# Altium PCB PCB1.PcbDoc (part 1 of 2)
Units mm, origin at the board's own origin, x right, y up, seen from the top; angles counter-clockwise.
Board outline 200 x 200.6 mm, 2 copper layers (Top Layer, Bottom Layer); 119 components, 156 nets, 629 pads, 125 vias.
Unrouted connection lines stored in the file: 2.
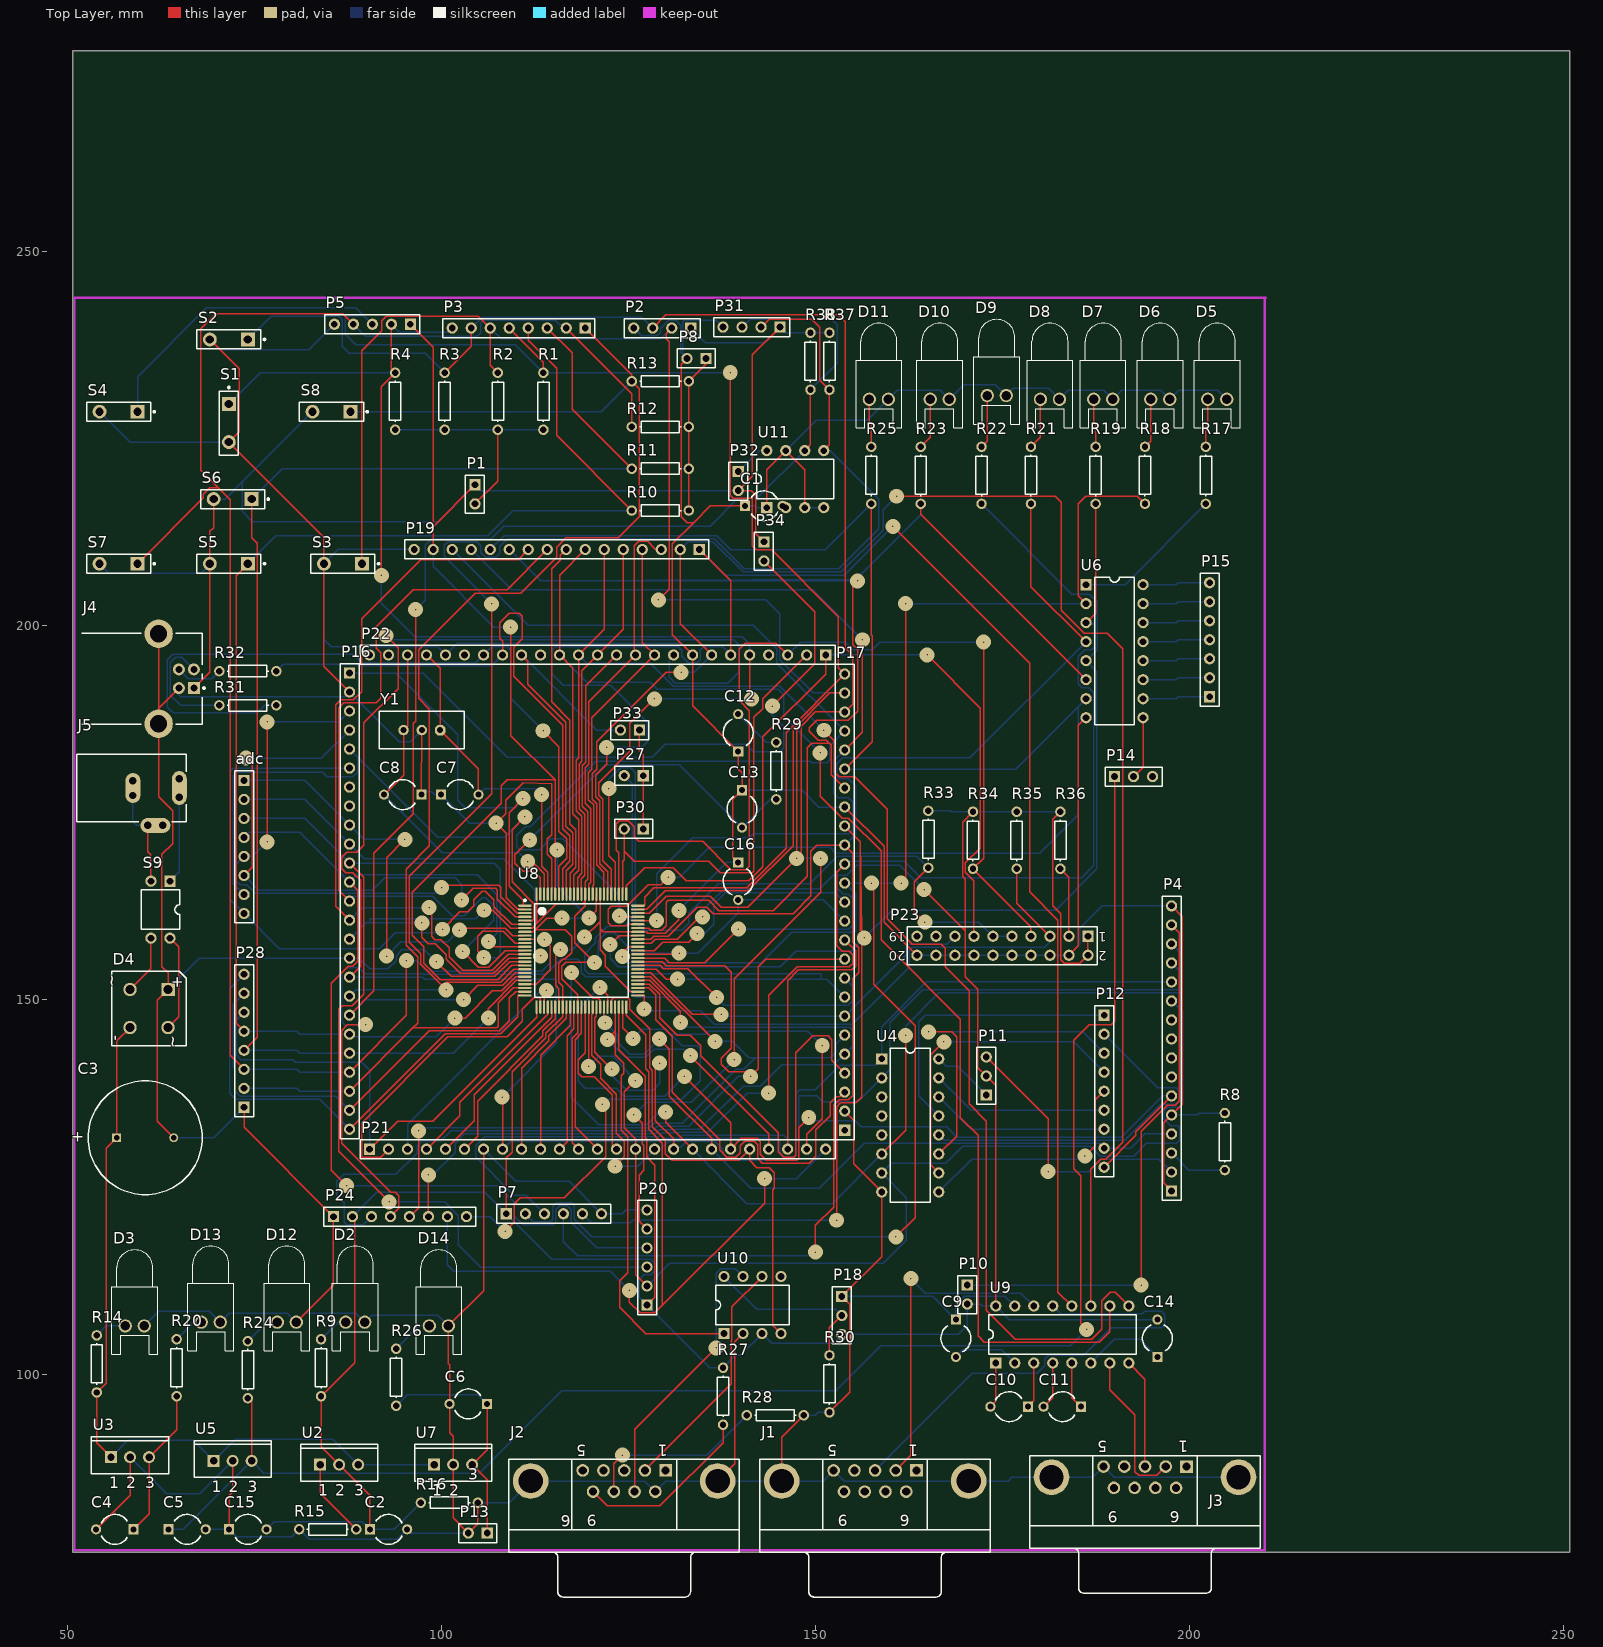
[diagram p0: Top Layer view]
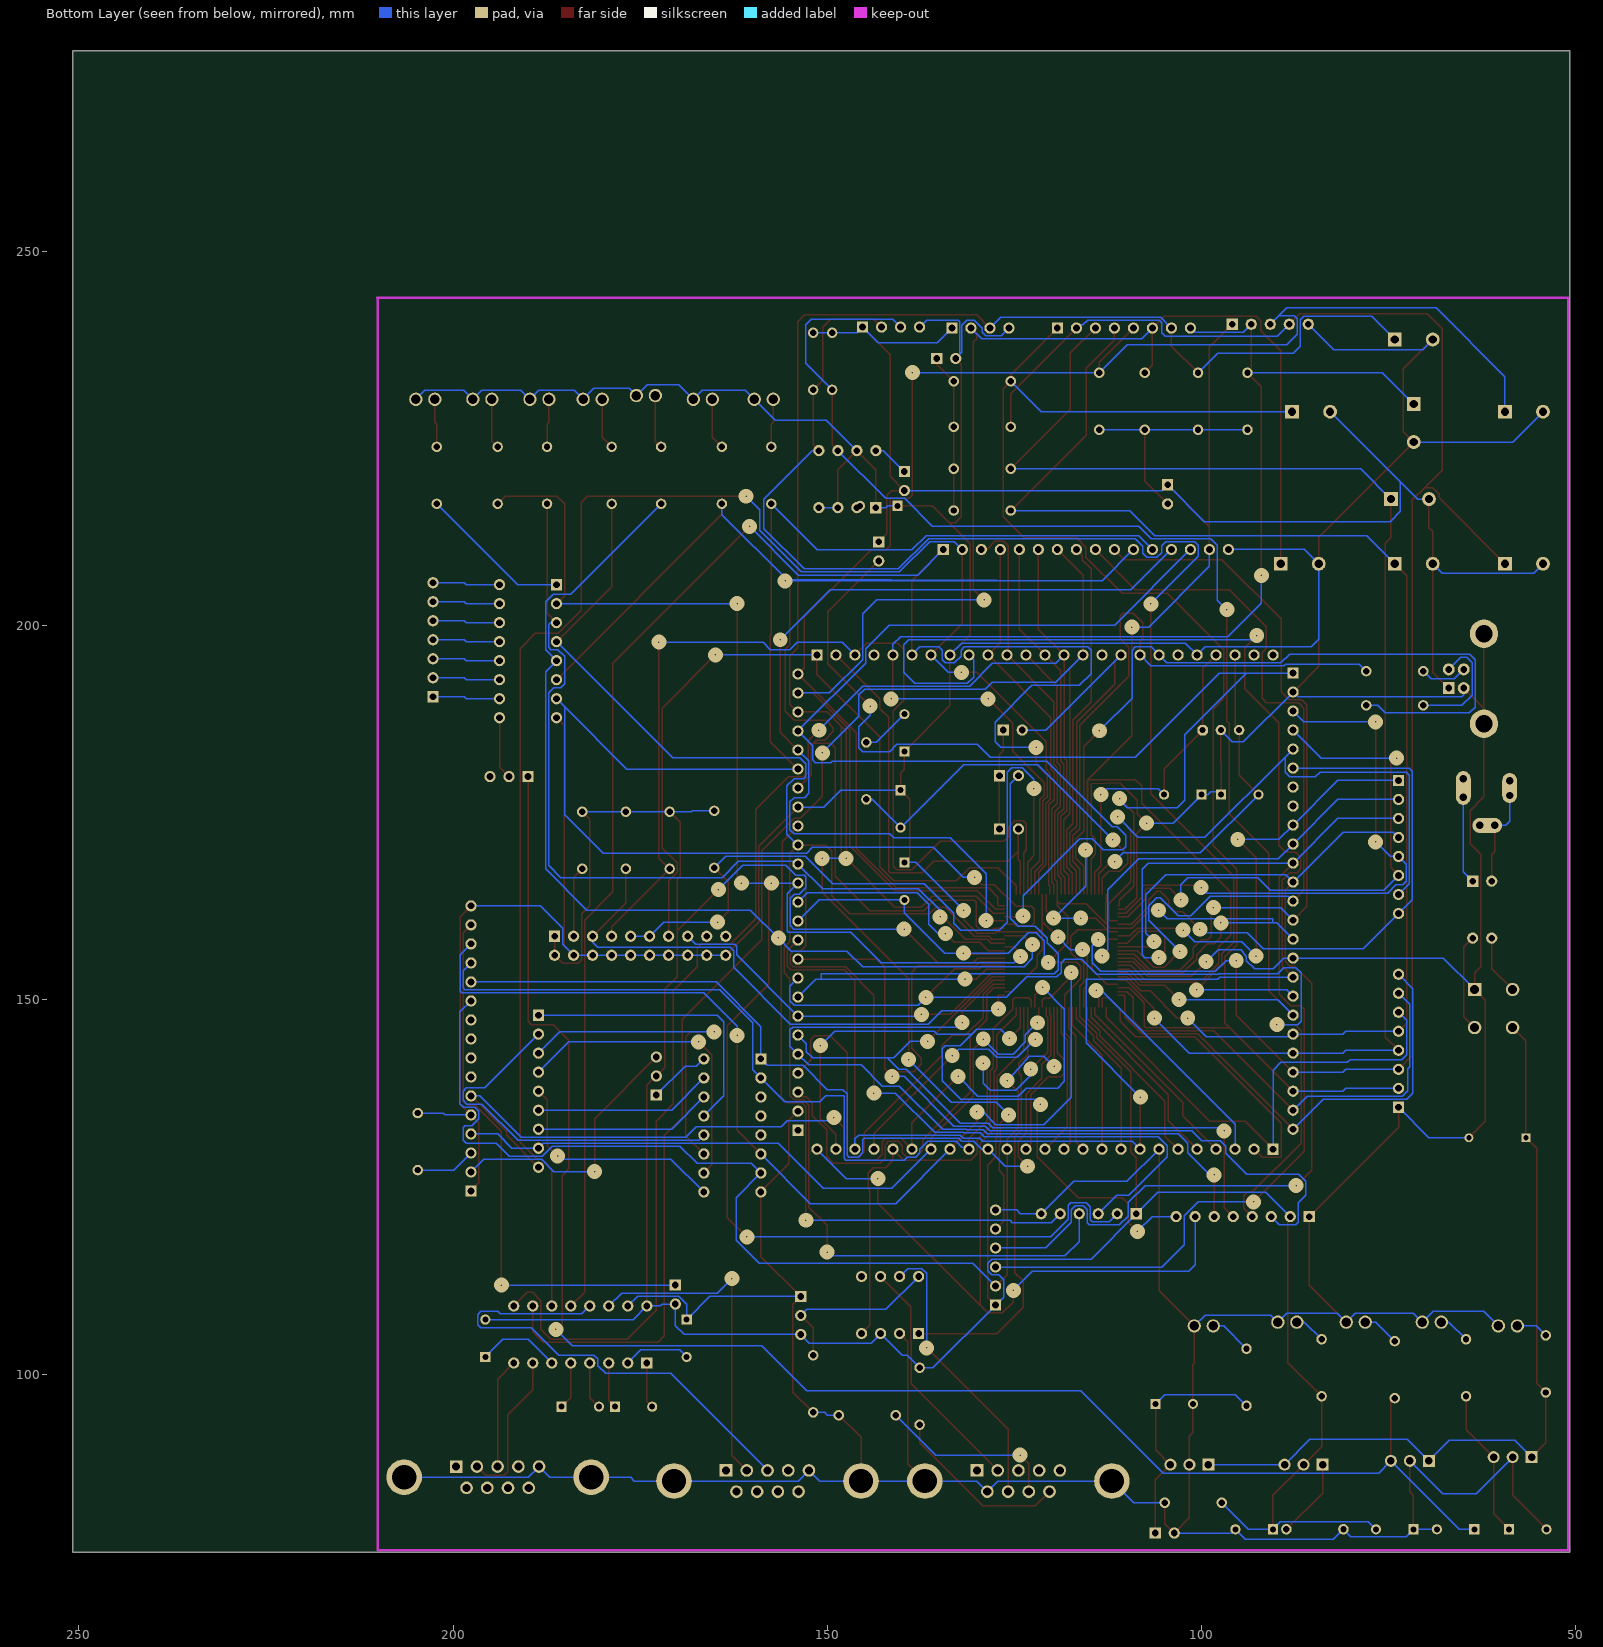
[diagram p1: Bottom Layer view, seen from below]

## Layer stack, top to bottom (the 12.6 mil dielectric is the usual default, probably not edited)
Top Layer: signal copper 0.0356
Dielectric: dielectric 0.32, FR-4, Dk 4.8
Bottom Layer: signal copper 0.0356

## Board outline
50.8,76.2 250.8,76.2 250.8,276.8 50.8,276.8

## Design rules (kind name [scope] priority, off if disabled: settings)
Clearance [All] p1: gap=0.2
ComponentClearance [All] p1: gap=0.254 collisioncheckmode=3 verticalgap=0.254
PolygonConnect [All] p1: connectstyle=Relief reliefconductorwidth=0.254 reliefentries=4 polygonreliefangle="90 Angle"
RoomDefinition relevance [InComponentClass('relevance')] p1: confinementstyle=ConfineIn formatcopy=TRUE lockcomponents=FALSE outline 0,0 50.8,0 50.8,25.4 0,25.4
RoutingVias [All] p1: holewidth=0.2 width=2 viastyle="Through Hole" minholewidth=0.711 minwidth=1.27 maxholewidth=0.711 maxwidth=1.27
SolderMaskExpansion [All] p1: expansion=0.102
TestPointUsage [All] p1: valid=0 allowmultiple=FALSE
Testpoint [All] p1: side=15 testpointundercomponent=TRUE minsize=1.016 maxsize=2.54 preferedsize=1.524 minholesize=0 maxholesize=1.016 preferedholesize=0.813 testpointgrid=0.025 style=1023 order=0123456789
Width [All] p1: maxlimit=0.2 minlimit=0.2 preferedwidth=0.2
18 further rules are at their usual default settings.

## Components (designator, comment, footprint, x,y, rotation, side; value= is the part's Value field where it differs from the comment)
adc "Header 8" HDR1X8 73.66,179.324 r270 top
C1 "Cap2" CAPR5-4X5 143.129,216.027 r0 top
C2 "Cap2" CAPR5-4X5 92.964,79.248 r0 top
C3 "Cap Pol1" RB7.6-15 60.452,131.572 r180 top
C4 "Cap2" CAPR5-4X5 56.388,79.248 r180 top
C5 "Cap2" CAPR5-4X5 66.04,79.248 r0 top
C6 "Cap2" CAPR5-4X5 103.632,96.012 r180 top
C7 "Cap2" CAPR5-4X5 102.489,177.419 r0 top
C8 "Cap2" CAPR5-4X5 94.869,177.419 r180 top
C9 "Cap2" CAPR5-4X5 168.783,104.775 r270 top
C10 "Cap2" CAPR5-4X5 175.895,95.631 r180 top
C11 "Cap2" CAPR5-4X5 183.007,95.631 r180 top
C12 "Cap2" CAPR5-4X5 139.7,185.674 r90 top
C13 "Cap2" CAPR5-4X5 140.208,175.514 r270 top
C14 "Cap2" CAPR5-4X5 195.707,104.775 r90 top
C15 "Cap2" CAPR5-4X5 74.168,79.248 r0 top
C16 "Cap2" CAPR5-4X5 139.7,165.862 r270 top
D2 "LED0" LED-0 88.519,106.934 r180 top
D3 "LED0" LED-0 59.055,106.426 r180 top
D4 "Bridge1" D-38 60.96,148.844 r270 top
D5 "LED0" LED-0 203.708,230.251 r180 top
D6 "LED0" LED-0 196.088,230.251 r180 top
D7 "LED0" LED-0 188.468,230.251 r180 top
D8 "LED0" LED-0 181.356,230.251 r180 top
D9 "LED0" LED-0 174.244,230.759 r180 top
D10 "LED0" LED-0 166.624,230.251 r180 top
D11 "LED0" LED-0 158.496,230.251 r180 top
D12 "LED0" LED-0 79.375,106.934 r180 top
D13 "LED0" LED-0 69.215,106.934 r180 top
D14 "LED0" LED-0 99.695,106.426 r180 top
J1 "D Connector 9" DSUB1.385-2H9 157.988,76.2 r180 top
J2 "D Connector 9" DSUB1.385-2H9 124.46,76.2 r180 top
J3 "D Connector 9" DSUB1.385-2H9 194.056,76.708 r180 top
J4 "1-1470156-1" 1-1470156 51.943,192.913 r180 top
J5 "PWR2.5" KLD-0202 51.308,178.308 r0 top
P1 "pad/sw" HDR1X2 104.521,218.821 r270 top
P2 "Debug Unit" HDR1X4 133.35,239.776 r180 top
P3 "keypad4*4" HDR1X8 119.253,239.776 r180 top
P4 "LCD2*16" HDR1X16 197.612,124.46 r90 top
P5 "Interrupt" HDR1X5 95.885,240.284 r180 top
P7 "pwm" HDR1X6 108.712,121.412 r0 top
P8 "pad/sw" HDR1X2 135.382,235.712 r180 top
P10 "LIGHT on/off" HDR1X2 170.307,111.887 r270 top
P11 "lcd/7seg" HDR1X3 172.847,137.287 r90 top
P12 "7SEGMENT*2" HDR1X9 188.595,147.955 r270 top
P13 "Header 2" HDR1X2 106.172,78.74 r180 top
P14 "5v/12v" HDR1X3 189.992,179.832 r0 top
P15 "12/5 v . 500ma out" HDR1X7 202.692,190.5 r90 top
P16 "1-25" HDR1X25 87.757,193.675 r270 top
P17 "51-75" HDR1X25 153.924,132.588 r90 top
P18 "Header 3" HDR1X3 153.543,110.363 r270 top
P19 "USART" HDR1X16 134.493,210.185 r180 top
P20 "Programmable Clock Output" HDR1X6 127.508,109.22 r90 top
P21 "26-50" HDR1X25 90.424,130.048 r0 top
P22 "76-100" HDR1X25 151.384,196.088 r180 top
P23 "Header 10X2" HDR2X10 186.436,158.496 r180 top
P24 "Synchronous Serial Controller" HDR1X8 85.598,121.031 r0 top
P27 "TST" HDR1X2 127,179.959 r180 top
P28 "Serial Peripheral Interface (SPI)" HDR1X8 73.66,135.636 r90 top
P30 "ERASE" HDR1X2 127,172.847 r180 top
P31 "2-wire" HDR1X4 145.288,239.903 r180 top
P32 "Header 2" HDR1X2 139.7,220.599 r270 top
P33 "JTAGSEL" HDR1X2 126.492,186.055 r180 top
P34 "Header 2" HDR1X2 143.129,211.201 r270 top
R1 "Res1" AXIAL-0.3 113.665,229.997 r270 top
R2 "Res1" AXIAL-0.3 107.569,229.997 r270 top
R3 "Res1" AXIAL-0.3 100.457,229.997 r270 top
R4 "Res1" AXIAL-0.3 93.853,229.997 r270 top
R8 "Res1" AXIAL-0.3 204.724,131.064 r90 top
R9 "Res1" AXIAL-0.3 83.947,100.838 r90 top
R10 "Res1" AXIAL-0.3 129.286,215.392 r180 top
R11 "Res1" AXIAL-0.3 129.286,220.98 r180 top
R12 "Res1" AXIAL-0.3 129.286,226.568 r180 top
R13 "Res1" AXIAL-0.3 129.286,232.664 r180 top
R14 "Res1" AXIAL-0.3 53.975,101.346 r90 top
R15 "Res1" AXIAL-0.3 84.836,79.248 r0 top
R16 "Res1" AXIAL-0.3 101.092,82.804 r180 top
R17 "Res1" AXIAL-0.3 202.184,220.091 r90 top
R18 "Res1" AXIAL-0.3 194.056,220.091 r90 top
R19 "Res1" AXIAL-0.3 187.452,220.091 r90 top
R20 "Res1" AXIAL-0.3 64.643,100.838 r90 top
R21 "Res1" AXIAL-0.3 178.816,220.091 r90 top
R22 "Res1" AXIAL-0.3 172.212,220.091 r90 top
R23 "Res1" AXIAL-0.3 164.084,220.091 r90 top
R24 "Res1" AXIAL-0.3 74.168,100.584 r90 top
R25 "Res1" AXIAL-0.3 157.48,220.091 r90 top
R26 "Res1" AXIAL-0.3 93.98,99.568 r90 top
R27 "Res1" AXIAL-0.3 137.668,97.028 r90 top
R28 "Res1" AXIAL-0.3 144.653,94.488 r0 top
R29 "Res1" AXIAL-0.3 144.78,180.594 r270 top
R30 "Res1" AXIAL-0.3 151.892,98.679 r90 top
R31 "Res1" AXIAL-0.3 74.168,189.357 r0 top
R32 "Res1" AXIAL-0.3 74.168,193.929 r0 top
R33 "Res1" AXIAL-0.3 165.1,171.45 r90 top
R34 "Res1" AXIAL-0.3 171.069,171.323 r90 top
R35 "Res1" AXIAL-0.3 176.911,171.323 r90 top
R36 "Res1" AXIAL-0.3 182.753,171.323 r90 top
R37 "Res1" AXIAL-0.3 151.892,235.331 r90 top
R38 "Res1" AXIAL-0.3 149.352,235.331 r90 top
S1 "SW-PB" SPST-2 71.628,227.076 r270 top
S2 "SW-PB" SPST-2 71.628,238.252 r180 top
S3 "SW-PB" SPST-2 86.868,208.28 r180 top
S4 "SW-PB" SPST-2 56.896,228.6 r180 top
S5 "SW-PB" SPST-2 71.628,208.28 r180 top
S6 "SW-PB" SPST-2 72.136,216.916 r180 top
S7 "SW-PB" SPST-2 56.896,208.28 r180 top
S8 "SW-PB" SPST-2 85.344,228.6 r180 top
S9 "SW DIP-2" DIP-4 62.484,162.052 r180 top
U2 "LM317T" 221A-04 86.36,87.884 r0 top
U3 "MC78M12BT" 221A-04 58.42,88.9 r0 top
U4 "DM7447AN" N16E 162.687,133.223 r270 top
U5 "MC78M05CT" 221A-04 72.136,88.392 r0 top
U6 "ULN2003A" A16 189.992,196.596 r270 top
U7 "MC78M05CT" 221A-04 101.6,87.884 r0 top
U8 "AT91SAM7X256-AU" LQFP100_N 118.745,156.591 r0 top
U9 "MAX232ACPE" PE16A 183.007,105.283 r0 top
U10 "MCP2551-E/P" PDIP300-8 141.605,109.22 r0 top
U11 "ST24E256B6" PSDIP8A 147.32,219.583 r0 top
Y1 "ECS-49-20-4-3IL" HC-49US 97.409,186.055 r180 top

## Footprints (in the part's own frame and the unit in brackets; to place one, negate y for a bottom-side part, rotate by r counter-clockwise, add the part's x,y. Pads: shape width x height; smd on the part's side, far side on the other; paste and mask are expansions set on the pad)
1-1470156 [mm] "Connector; USB1.1, Type B, Thru-Hole; 4 Position; Right Angle"
  rect 1.6x1.6 hole 0.92: 1(-15.01,1.25)
  round 1.6 hole 0.92: 2(-15.01,-1.25) 3(-13.01,-1.25) 4(-13.01,1.25)
  round 3.8 hole 2.3: 5(-10.3,6.02) 6(-10.3,-6.02)
  silkscreen extent -16.49,-6.05 -0.02,6.05
221A-04 [mm] "TO, Thru-Hole, Vertical, Heatsink Mounted; 3 In-Line Leads; Pitch 2.54 mm"
  rect 1.6x1.6 hole 1: 1(-2.54,0)
  round 1.6 hole 1: 2(0,0) 3(2.54,0)
  silkscreen extent -5.15,-2.2 5.15,2.7
A16 [mm] "DIP; 16 Leads; Row Spacing 7.62 mm; Pitch 2.54 mm"
  rect 1.5x1.5 hole 0.9: 1(-8.89,-3.81)
  round 1.5 hole 0.9: 2(-6.35,-3.81) 3(-3.81,-3.81) 4(-1.27,-3.81) 5(1.27,-3.81) 6(3.81,-3.81) 7(6.35,-3.81) 8(8.89,-3.81) 9(8.89,3.81) 10(6.35,3.81) 11(3.81,3.81) 12(1.27,3.81) 13(-1.27,3.81) 14(-3.81,3.81) 15(-6.35,3.81) 16(-8.89,3.81)
  silkscreen extent -9.85,-2.65 9.85,2.65
AXIAL-0.3 [mm] "Resistor; 2 Leads"
  round 1.4 hole 0.85: 1(-3.81,0) 2(3.81,0)
  silkscreen extent -2.77,-0.76 2.77,0.76
CAPR5-4X5 [mm] "Capacitor; 2 Leads"
  rect 1.35x1.35 hole 0.8: 1(-2.5,0)
  round 1.35 hole 0.8: 2(2.5,0)
  silkscreen extent -1.69,-2 1.82,2
D-38 [mm] "Bridge Rectifier; 4 Terminals; Body 9.4 x 9.4 mm (typ); Pitch 5.08 mm"
  rect 1.8x1.8 hole 1.2: 1(-2.54,2.54)
  round 1.8 hole 1.2: 2(-2.54,-2.54) 3(2.54,-2.54) 4(2.54,2.54)
  silkscreen extent -5,-5 5,5
DIP-4 [mm] "DIP; 4 Leads; Row Spacing 7.62 mm; Pitch 2.54 mm"
  rect 1.5x1.5 hole 0.9: 1(-1.27,-3.81)
  round 1.5 hole 0.9: 2(1.27,-3.81) 3(1.27,3.81) 4(-1.27,3.81)
  silkscreen extent -2.55,-2.65 2.55,2.65
DSUB1.385-2H9 [mm] "Connector; D Subminiature; 9 Position; Right Angle; Pitch 1.385 mm"
  rect 1.69x1.69 hole 1.09: 1(-5.54,-10.92)
  round 1.69 hole 1.09: 2(-2.77,-10.92) 3(0,-10.92) 4(2.77,-10.92) 5(5.54,-10.92) 6(-4.155,-8.08) 7(-1.385,-8.08) 8(1.385,-8.08) 9(4.155,-8.08)
  round 4.76 hole 3.26: 10(-12.495,-9.5) 11(12.495,-9.5)
  silkscreen extent -15.4,-12.4 15.4,6
HC-49US [mm] "Quartz Crystal, Thru-Hole; 3 Leads; Body 11.35 x 5 x 3.5 mm (LxWxH max)"
  oct 1.4x1.4 hole 0.8: 1(-2.44,0)
  round 1.4 hole 0.8: 2(0,0) 3(2.44,0)
  silkscreen extent -5.7,-2.5 5.7,2.5
HDR1X2 [mm] "Connector; Header; 2 Position"
  rect 1.5x1.5 hole 0.9: 1(0,0)
  round 1.5 hole 0.9: 2(2.54,0)
  silkscreen extent -1.27,-1.27 3.81,1.27
HDR1X3 [mm] "Connector; Header; 3 Position"
  rect 1.5x1.5 hole 0.9: 1(0,0)
  round 1.5 hole 0.9: 2(2.54,0) 3(5.08,0)
  silkscreen extent -1.27,-1.27 6.35,1.27
HDR1X4 [mm] "Connector; Header; 4 Position"
  rect 1.5x1.5 hole 0.9: 1(0,0)
  round 1.5 hole 0.9: 2(2.54,0) 3(5.08,0) 4(7.62,0)
  silkscreen extent -1.27,-1.27 8.89,1.27
HDR1X5 [mm] "Connector; Header; 5 Position"
  rect 1.5x1.5 hole 0.9: 1(0,0)
  round 1.5 hole 0.9: 2(2.54,0) 3(5.08,0) 4(7.62,0) 5(10.16,0)
  silkscreen extent -1.27,-1.27 11.43,1.27
HDR1X6 [mm] "Connector; Header; 6 Position"
  rect 1.5x1.5 hole 0.9: 1(0,0)
  round 1.5 hole 0.9: 2(2.54,0) 3(5.08,0) 4(7.62,0) 5(10.16,0) 6(12.7,0)
  silkscreen extent -1.27,-1.27 13.97,1.27
HDR1X7 [mm] "Connector; Header; 7 Position"
  rect 1.5x1.5 hole 0.9: 1(0,0)
  round 1.5 hole 0.9: 2(2.54,0) 3(5.08,0) 4(7.62,0) 5(10.16,0) 6(12.7,0) 7(15.24,0)
  silkscreen extent -1.27,-1.27 16.51,1.27
HDR1X8 [mm] "Connector; Header; 8 Position"
  rect 1.5x1.5 hole 0.9: 1(0,0)
  round 1.5 hole 0.9: 2(2.54,0) 3(5.08,0) 4(7.62,0) 5(10.16,0) 6(12.7,0) 7(15.24,0) 8(17.78,0)
  silkscreen extent -1.27,-1.27 19.05,1.27
HDR1X9 [mm] "Connector; Header; 9 Position"
  rect 1.5x1.5 hole 0.9: 1(0,0)
  round 1.5 hole 0.9: 2(2.54,0) 3(5.08,0) 4(7.62,0) 5(10.16,0) 6(12.7,0) 7(15.24,0) 8(17.78,0) 9(20.32,0)
  silkscreen extent -1.27,-1.27 21.59,1.27
HDR1X16 [mm] "Connector; Header; 16 Position"
  rect 1.5x1.5 hole 0.9: 1(0,0)
  round 1.5 hole 0.9: 2(2.54,0) 3(5.08,0) 4(7.62,0) 5(10.16,0) 6(12.7,0) 7(15.24,0) 8(17.78,0) 9(20.32,0) 10(22.86,0) 11(25.4,0) 12(27.94,0) 13(30.48,0) 14(33.02,0) 15(35.56,0) 16(38.1,0)
  silkscreen extent -1.27,-1.27 39.37,1.27
HDR1X25 [mm] "Connector; Header; 25 Position"
  rect 1.5x1.5 hole 0.9: 1(0,0)
  round 1.5 hole 0.9: 2(2.54,0) 3(5.08,0) 4(7.62,0) 5(10.16,0) 6(12.7,0) 7(15.24,0) 8(17.78,0) 9(20.32,0) 10(22.86,0) 11(25.4,0) 12(27.94,0) 13(30.48,0) 14(33.02,0) 15(35.56,0) 16(38.1,0) 17(40.64,0) 18(43.18,0) 19(45.72,0) 20(48.26,0) 21(50.8,0) 22(53.34,0) 23(55.88,0) 24(58.42,0) 25(60.96,0)
  silkscreen extent -1.27,-1.27 62.23,1.27
HDR2X10 [mm] "Connector; Header; 10x2 Position"
  rect 1.5x1.5 hole 0.9: 1(0,0)
  round 1.5 hole 0.9: 2(0,2.54) 3(2.54,0) 4(2.54,2.54) 5(5.08,0) 6(5.08,2.54) 7(7.62,0) 8(7.62,2.54) 9(10.16,0) 10(10.16,2.54) 11(12.7,0) 12(12.7,2.54) 13(15.24,0) 14(15.24,2.54) 15(17.78,0) 16(17.78,2.54) 17(20.32,0) 18(20.32,2.54) 19(22.86,0) 20(22.86,2.54)
  silkscreen extent -1.27,-1.27 24.13,3.81
KLD-0202 [mm] "DC Power Jack, 2.5mm, KLD Series, PCB Mount"
  oval 2x4.5 all layers, no hole: 1(13.7,0)
  round 1.5 hole 1: 1A(13.7,-1.25) 1B(13.7,1.25) 2A(7.5,-1) 2B(7.5,1) 3A(9.5,-5) 3B(11.5,-5)
  oval 2x4 all layers, no hole: 2(7.5,0)
  oval 4x2 all layers, no hole: 3(10.5,-5)
  silkscreen extent 0,-4.5 14.6,4.5
LED-0 [mil] "Typical INFRARED GaAs LED; 2 Leads"
  round 70 hole 50: 1(50,0) 2(-50,0)
  silkscreen extent -120,-400 120,150
LQFP100_N [mm] "Thin QFP, 100-Leads, Body 14x14mm, Pitch 0.5mm, IPC Medium Density"
  oval 1.8x0.3 smd: 1(-7.55,6) 2(-7.55,5.5) 3(-7.55,5) 4(-7.55,4.5) 5(-7.55,4) 6(-7.55,3.5) 7(-7.55,3) 8(-7.55,2.5) 9(-7.55,2) 10(-7.55,1.5) 11(-7.55,1) 12(-7.55,0.5) 13(-7.55,0) 14(-7.55,-0.5) 15(-7.55,-1) 16(-7.55,-1.5) 17(-7.55,-2) 18(-7.55,-2.5) 19(-7.55,-3) 20(-7.55,-3.5) 21(-7.55,-4) 22(-7.55,-4.5) 23(-7.55,-5) 24(-7.55,-5.5) 25(-7.55,-6) 51(7.55,-6) 52(7.55,-5.5) 53(7.55,-5) 54(7.55,-4.5) 55(7.55,-4) 56(7.55,-3.5) 57(7.55,-3) 58(7.55,-2.5) 59(7.55,-2) 60(7.55,-1.5) 61(7.55,-1) 62(7.55,-0.5) 63(7.55,0) 64(7.55,0.5) 65(7.55,1) 66(7.55,1.5) 67(7.55,2) 68(7.55,2.5) 69(7.55,3) 70(7.55,3.5) 71(7.55,4) 72(7.55,4.5) 73(7.55,5) 74(7.55,5.5) 75(7.55,6)
  oval 0.3x1.8 smd: 26(-6,-7.55) 27(-5.5,-7.55) 28(-5,-7.55) 29(-4.5,-7.55) 30(-4,-7.55) 31(-3.5,-7.55) 32(-3,-7.55) 33(-2.5,-7.55) 34(-2,-7.55) 35(-1.5,-7.55) 36(-1,-7.55) 37(-0.5,-7.55) 38(0,-7.55) 39(0.5,-7.55) 40(1,-7.55) 41(1.5,-7.55) 42(2,-7.55) 43(2.5,-7.55) 44(3,-7.55) 45(3.5,-7.55) 46(4,-7.55) 47(4.5,-7.55) 48(5,-7.55) 49(5.5,-7.55) 50(6,-7.55) 76(6,7.55) 77(5.5,7.55) 78(5,7.55) 79(4.5,7.55) 80(4,7.55) 81(3.5,7.55) 82(3,7.55) 83(2.5,7.55) 84(2,7.55) 85(1.5,7.55) 86(1,7.55) 87(0.5,7.55) 88(0,7.55) 89(-0.5,7.55) 90(-1,7.55) 91(-1.5,7.55) 92(-2,7.55) 93(-2.5,7.55) 94(-3,7.55) 95(-3.5,7.55) 96(-4,7.55) 97(-4.5,7.55) 98(-5,7.55) 99(-5.5,7.55) 100(-6,7.55)
  silkscreen extent -7.67,-6.25 6.25,6.82, body extent -7,-7 7,7, height 1.6
N16E [mm] "DIP; 16 Leads; Row Spacing 7.62 mm; Pitch 2.54 mm"
  rect 1.5x1.5 hole 0.9: 1(-8.89,-3.81)
  round 1.5 hole 0.9: 2(-6.35,-3.81) 3(-3.81,-3.81) 4(-1.27,-3.81) 5(1.27,-3.81) 6(3.81,-3.81) 7(6.35,-3.81) 8(8.89,-3.81) 9(8.89,3.81) 10(6.35,3.81) 11(3.81,3.81) 12(1.27,3.81) 13(-1.27,3.81) 14(-3.81,3.81) 15(-6.35,3.81) 16(-8.89,3.81)
  silkscreen extent -10.3,-2.65 10.3,2.65
PDIP300-8 [mm] "DIP, Plastic; 8 Leads; Row Spacing 7.62 mm; Pitch 2.54 mm"
  rect 1.5x1.5 hole 0.9: 1(-3.81,-3.81)
  round 1.5 hole 0.9: 2(-1.27,-3.81) 3(1.27,-3.81) 4(3.81,-3.81) 5(3.81,3.81) 6(1.27,3.81) 7(-1.27,3.81) 8(-3.81,3.81)
  silkscreen extent -4.9,-2.65 4.9,2.65
PE16A [mm] "DIP; 16 Leads; Row Spacing 7.62 mm; Pitch 2.54 mm"
  rect 1.5x1.5 hole 0.9: 1(-8.89,-3.81)
  round 1.5 hole 0.9: 2(-6.35,-3.81) 3(-3.81,-3.81) 4(-1.27,-3.81) 5(1.27,-3.81) 6(3.81,-3.81) 7(6.35,-3.81) 8(8.89,-3.81) 9(8.89,3.81) 10(6.35,3.81) 11(3.81,3.81) 12(1.27,3.81) 13(-1.27,3.81) 14(-3.81,3.81) 15(-6.35,3.81) 16(-8.89,3.81)
  silkscreen extent -9.85,-2.65 9.85,2.65
PSDIP8A [mm] "DIP; 8 Leads; Row Spacing 7.62 mm; Pitch 2.54 mm"
  rect 1.5x1.5 hole 0.9: 1(-3.81,-3.81)
  round 1.5 hole 0.9: 2(-1.27,-3.81) 3(1.27,-3.81) 4(3.81,-3.81) 5(3.81,3.81) 6(1.27,3.81) 7(-1.27,3.81) 8(-3.81,3.81)
  silkscreen extent -5.15,-2.65 5.15,2.65
RB7.6-15 [mm] "Polarized Capacitor (Radial); 2 Leads"
  rect 1.2x1.2 hole 0.7: 1(3.81,0)
  round 1.2 hole 0.7: 2(-3.81,0)
  silkscreen extent -7.62,-7.62 7.62,7.62
SPST-2 [mm] "Circuit Breaker; 2 Leads"
  rect 1.85x1.85 hole 1.1: 1(-2.54,0)
  round 1.85 hole 1.1: 2(2.54,0)
  silkscreen extent -4.89,-1.27 4.28,1.27

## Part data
adc: "Header, 8-Pin"
C1 C2 C4 C5 C6 C7 C8 C9 C10 C11 C12 C13 C14 C15 C16: "Capacitor"
C3: "Polarized Capacitor (Radial)"
D2 D3 D5 D6 D7 D8 D9 D10 D11 D12 D13 D14: "Typical INFRARED GaAs LED"
D4: "Full Wave Diode Bridge"
J1 J2 J3: "Receptacle Assembly, 9 Position, Right Angle"
J4: "USB 1.1, Right Angle, Thru-Hole, B Type, Receptacle, 4 Position, White"
J5: "Low Voltage Power Supply Connector"
P1 P8 P10 P27 P30 P33: library part "Header 2", "Header, 2-Pin"
P2 P31: library part "Header 4", "Header, 4-Pin"
P3 P24 P28: library part "Header 8", "Header, 8-Pin"
P4 P19: library part "Header 16", "Header, 16-Pin"
P5: library part "Header 5", "Header, 5-Pin"
P7 P20: library part "Header 6", "Header, 6-Pin"
P11 P14: library part "Header 3", "Header, 3-Pin"
P12: library part "Header 9", "Header, 9-Pin"
P13 P32 P34: "Header, 2-Pin"
P15: library part "Header 7", "Header, 7-Pin"
P16 P17 P21 P22: library part "Header 25", "Header, 25-Pin"
P18: "Header, 3-Pin"
P23: "Header, 10-Pin, Dual row"
R1 R2 R3 R4 R8 R9 R10 R11 R12 R13 R14 R15 R16 R17 R18 R19 R20 R21 R22 R23 R24 R25 R26 R27 R28 R29 R30 R31 R32 R33 R34 R35 R36 R37 R38: "Resistor"
S1 S2 S3 S4 S5 S6 S7 S8: "Switch"
S9: "DIP Switch, 2 Position, SPST"
U2: "3-Terminal Adjustable Positive Voltage Regulator"
U3 U5 U7: "3-Terminal Medium-Current Positive Fixed Voltage Regulator"
U4: "BCD to 7-Segment Decoder/Driver"
U6: "High-Voltage, High-Current Darlington Array"
U8: "Smart ARM Microcontroller, ARM7TDMI 32-Bit RISC CPU, 256KB Flash and 64KB SRAM, 100-Pin LQFP, Industrial, Pb-Free"
U9: "+5V Powered, Multi-Channel RS-232 Driver/Receiver"
U10: "High Speed CAN Transceiver, 8-Pin Plastic DIP, Extended Grade"
U11: "Serial Access Extended Addressing Compatible with I²C Bus 256K (32K x 8) EEPROM"
Y1: "Crystal Oscillator, 3rd In-Line Lead Version"

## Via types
v1: diameter 2, hole 0.2, Top Layer to Bottom Layer, 125 vias

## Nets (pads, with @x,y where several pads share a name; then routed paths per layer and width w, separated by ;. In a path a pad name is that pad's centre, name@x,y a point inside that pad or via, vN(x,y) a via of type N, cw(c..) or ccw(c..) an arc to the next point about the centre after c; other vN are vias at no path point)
5V: C5.1 P14.1 R24.1 U5.3 | length 222.3
  Top Layer w0.2: R24.1@74.168,96.774 74.676,96.266 U5.3@74.676,88.392 ; v1(186.258,105.969) 185.445,106.782 185.445,126.525 184.552,127.419 184.552,144.598 186.639,146.685 189.56,146.685 189.992,147.117 P14.1@189.992,179.832
  Bottom Layer w0.2: C5.1@63.54,79.248 65.532,79.248 U5.3@74.676,88.392 76.302,86.766 105.105,86.766 116.103,97.765 152.73,97.765 158.775,103.81 184.099,103.81 v1(186.258,105.969)
12V: C4.1 R20.1 U3.3 | length 20.2
  Top Layer w0.2: C4.1@58.888,79.248 60.96,81.32 U3.3@60.96,88.9 64.643,92.583 R20.1@64.643,97.028
+12: P14.3
AD4: adc.5 P16.3 U8.3 | length 77.2
  Top Layer w0.2: v1(76.733,171.12) v1(76.733,187.147) ; v1(100.051,164.998) 100.347,165.295 107.696,165.295 107.938,165.053 107.938,163.791 110.138,161.591 U8.3@111.195,161.591
  Bottom Layer w0.2: v1(76.733,171.12) 74.778,169.164 adc.5@73.66,169.164 72.61,168.114 72.61,165.871 73.127,165.354 74.016,165.354 75.125,164.245 99.297,164.245 v1(100.051,164.998) ; v1(76.733,187.147) 86.309,187.147 P16.3@87.757,188.595
AD5: adc.6 P16.4 U8.4 | length 76.2
  Top Layer w0.2: adc.6@73.66,166.624 74.727,167.691 74.727,181.483 v1(73.914,182.296) ; v1(102.743,163.373) 104.265,164.895 107.29,164.895 107.528,164.657 107.528,163.441 109.877,161.091 U8.4@111.195,161.091
  Bottom Layer w0.2: adc.6@73.66,166.624 75.639,164.645 90.807,164.645 92.461,166.298 101.849,166.298 102.743,165.405 v1(102.743,163.373) ; v1(73.914,182.296) 83.998,182.296 P16.4@87.757,186.055
AD6: adc.7 P16.5 U8.5 | length 82.1
  Top Layer w0.2: U8.5@111.195,160.591 112.166,160.591 112.395,160.82 112.395,162.839 109.467,165.768 109.467,172.713 v1(111.201,174.447)
  Bottom Layer w0.2: adc.7@73.66,164.084 72.21,165.534 72.21,179.991 72.61,180.391 84.15,180.391 84.76,179.781 88.189,179.781 88.824,180.416 88.824,182.448 ; P16.5@87.757,183.515 88.824,182.448 ; v1(111.201,174.447) 108.483,171.729 99.543,171.729 88.824,182.448
AD7: adc.8 P16.6 U8.6 | length 81.4
  Top Layer w0.2: v1(100.203,159.436) 102.514,161.747 103.556,161.747 104.369,162.56 104.369,163.373 105.491,164.495 105.913,164.495 107.036,163.373 107.036,162.463 109.408,160.091 U8.6@111.195,160.091
  Bottom Layer w0.2: P16.6@87.757,180.975 72.21,180.975 71.81,180.575 71.81,163.394 adc.8@73.66,161.544 78.359,156.845 91.731,156.845 93.869,158.983 99.75,158.983 v1(100.203,159.436)
ADVREF: C1.2 P16.1 P34.2 U8.1 | length 141
  Top Layer w0.2: v1(110.922,176.886) 109.067,175.031 109.067,165.213 110.973,163.308 110.973,162.591 U8.1@111.195,162.591 ; P34.2@143.129,208.661 149.911,201.879 149.911,194.894 v1(144.272,189.255)
  Bottom Layer w0.2: P16.1@87.757,193.675 94.005,193.675 ; v1(110.922,176.886) 110.922,176.7 109.889,175.666 103.226,175.666 102.235,176.657 102.235,185.445 94.005,193.675 ; v1(144.272,189.255) 144.272,188.036 145.796,186.512 145.796,183.693 145.263,183.159 141.681,183.159 140.691,184.15 129.946,184.15 128.219,182.423 108.864,182.423 97.612,193.675 94.005,193.675
CTS0: P19.5 P22.13 U8.88 | length 49
  Top Layer w0.2: U8.88@118.745,164.141 118.745,166.17 119.195,166.62 119.195,174.776 118.428,175.542 118.428,181.513 118.777,181.861 118.777,193.961 P22.13@120.904,196.088 124.333,199.517 P19.5@124.333,210.185
CTS1: P16.14 P19.10 U8.14 | length 100.8
  Top Layer w0.2: P16.14@87.757,160.655 85.907,162.505 85.907,189.429 86.563,190.085 88.282,190.085 89.357,191.16 89.357,200.92 97.276,208.839 110.287,208.839 P19.10@111.633,210.185 ; v1(98.4,162.331) 98.709,162.022 98.709,158.49 99.162,158.037 99.974,158.037 101.065,156.947 101.065,155.775 102.889,153.951 106.809,153.951 108.949,156.091 U8.14@111.195,156.091
  Bottom Layer w0.2: P16.14@87.757,160.655 89.433,162.331 v1(98.4,162.331)
DB4: P4.11 P20.2 P21.15 U4.7 U8.40 | length 158.4
  Top Layer w0.2: v1(119.693,141.105) 119.693,145.915 119.728,148.382 U8.40@119.745,149.041 ; v1(125.959,139.217) 124.455,137.714 124.455,132.914 125.984,131.385 P21.15@125.984,130.048 125.984,113.284 P20.2@127.508,111.76
  Bottom Layer w0.2: v1(119.693,141.105) 121.051,142.463 123.034,142.463 125.552,139.624 v1(125.959,139.217) ; P20.2@127.508,111.76 130.531,114.783 159.106,114.783 162.179,117.856 162.179,123.571 U4.7@158.877,126.873 160.147,128.143 167.411,128.143 169.702,130.434 186.736,130.434 188.062,129.108 192.532,129.108 194.234,130.81 198.222,130.81 198.679,131.267 198.679,132.893 198.425,133.147 197.51,133.147 196.562,134.095 196.562,135.128 197.104,135.67 198.611,135.67 199.085,136.144 199.085,148.387 P4.11@197.612,149.86
DB5: P4.12 P21.16 U4.1 U8.41 | length 118.6
  Top Layer w0.2: U8.41@120.245,149.041 120.245,148.123 120.128,148.006 120.128,142.61 121.31,141.427 121.31,139.522 123.419,137.414 123.419,132.19 124.494,131.115 124.494,129.015 v1(123.241,127.762)
  Bottom Layer w0.2: v1(123.241,127.762) 126.238,127.762 P21.16@128.524,130.048 129.362,130.048 130.412,131.098 132.01,131.098 132.41,131.498 145.049,131.498 145.254,131.293 145.254,129.613 145.869,128.998 147.117,128.998 147.354,129.235 147.354,137.421 147.93,137.996 149.975,137.996 153.245,141.266 158.03,141.266 U4.1@158.877,142.113 158.877,146.423 164.854,152.4 P4.12@197.612,152.4
DB6: P4.13 P21.17 U4.2 U8.42 | length 125.2
  Top Layer w0.2: U8.42@120.745,149.041 120.745,147.783 120.545,147.583 120.545,143.02 v1(122.809,140.756) ; v1(129.184,141.554) 128.632,141.001 128.632,133.838 131.064,131.406 P21.17@131.064,130.048
  Bottom Layer w0.2: v1(122.809,140.756) 122.809,139.903 124.799,137.914 128.243,137.914 129.184,138.856 v1(129.184,141.554) ; P21.17@131.064,130.048 131.064,130.315 132.017,130.315 132.8,131.098 136.584,131.098 137.634,130.048 137.634,129.54 138.176,128.998 139.334,128.998 139.734,128.598 147.523,128.598 147.754,128.829 147.754,137.163 147.781,137.19 150.19,137.19 150.982,136.398 155.702,136.398 U4.2@158.877,139.573 159.944,140.64 159.944,146.914 164.38,151.35 198.425,151.35 198.662,151.587 198.662,153.89 P4.13@197.612,154.94
DB7: P4.14 P21.18 U4.6 U8.43 | length 139.9
  Top Layer w0.2: v1(117.399,153.67) 117.399,153.137 120.294,150.241 120.966,150.241 121.245,149.962 U8.43@121.245,149.041 ; v1(129.997,135.019) 129.997,133.655 P21.18@133.604,130.048 ; U4.6@158.877,129.413 162.052,132.588 v1(162.052,145.263)
  Bottom Layer w0.2: v1(117.399,153.67) 117.399,136.986 121.065,133.32 127.462,133.32 129.16,135.019 v1(129.997,135.019) ; P21.18@133.604,130.048 140.868,122.784 152.248,122.784 U4.6@158.877,129.413 ; v1(162.052,145.263) 162.052,146.482 166.52,150.95 198.831,150.95 199.062,151.181 199.062,156.03 P4.14@197.612,157.48
DCD1: P17.19 P19.11 R23.1 U6.6 U8.69 | length 221.9
  Top Layer w0.2: U8.69@126.295,159.591 127.716,159.591 128.016,159.291 129.471,159.291 130.099,159.918 130.099,163.043 130.353,163.297 135.738,163.297 137.109,161.925 144.348,161.925 148.92,166.497 148.92,183.693 149.551,184.323 151.871,184.323 ; P17.19@153.924,178.308 152.121,180.111 152.121,184.074 151.871,184.323 ; v1(155.651,205.994) 154.986,205.329 154.986,197.485 155.651,196.82 155.651,188.57 154.432,187.35 150.165,187.35 149.2,186.385 149.2,185.877 150.368,184.709 151.486,184.709 151.871,184.323 ; R23.1@164.084,216.281 164.084,214.884 U6.6@186.182,192.786
  Bottom Layer w0.2: P19.11@109.093,210.185 113.284,205.994 ; v1(155.651,205.994) 113.284,205.994 ; R23.1@164.084,216.281 164.084,214.854 155.438,206.207 113.284,205.994
DDM: P22.18 R32.2 U8.93 | length 80.6
  Top Layer w0.2: P22.18@108.204,196.088 108.204,197.908 107.818,198.293 107.818,200.376 109.093,201.651 110.439,201.651 110.846,201.244 110.846,198.281 109.694,197.129 109.694,193.277 116.245,186.726 116.245,172.85 117.195,171.9 117.195,168.5 116.245,167.55 U8.93@116.245,164.141
  Bottom Layer w0.2: R32.2@77.978,193.929 78.918,194.869 88.743,194.869 88.974,194.638 106.754,194.638 P22.18@108.204,196.088
DDP: P22.19 R31.2 U8.94 | length 105.5
  Top Layer w0.2: v1(113.64,185.959) 115.745,183.854 115.745,172.55 116.795,171.5 116.795,168.9 115.745,167.85 U8.94@115.745,164.141
  Bottom Layer w0.2: R31.2@77.978,189.357 76.429,189.357 75.413,188.341 64.186,188.341 63.424,189.103 63.424,195.478 64.135,196.19 88.231,196.19 89.383,195.038 104.614,195.038 P22.19@105.664,196.088 106.731,197.155 108.814,197.155 109.271,196.698 109.271,190.328 v1(113.64,185.959)
DSR1: P17.20 P19.12 R25.1 U6.7 U8.70 | length 217.3
  Top Layer w0.2: U8.70@126.295,160.091 124.993,160.091 124.787,159.885 122.733,159.885 122.326,160.291 122.326,162.082 122.733,162.488 124.769,162.488 127.691,165.41 129.368,165.41 v1(130.327,166.37) ; P17.20@153.924,180.848 157.591,184.515 157.591,198.653 157.48,198.764 R25.1@157.48,216.281
  Bottom Layer w0.2: P19.12@106.553,210.185 108.403,212.035 136.809,212.035 138.709,210.134 151.333,210.134 R25.1@157.48,216.281 ; v1(130.327,166.37) 131.851,166.37 135.844,170.362 151.998,170.362 152.763,169.598 179.961,169.598 185.115,174.752 185.115,189.179 ; P17.20@153.924,180.848 176.784,180.848 185.115,189.179 ; U6.7@186.182,190.246 185.115,189.179
DTR1: P17.21 P19.13 U8.71 | length 123.5
  Top Layer w0.2: U8.71@126.295,160.591 v1(128.778,160.591) ; P17.21@153.924,183.388 156.286,185.75 v1(156.286,198.12)
  Bottom Layer w0.2: P19.13@104.013,210.185 109.423,204.775 149.631,204.775 v1(156.286,198.12) ; v1(128.778,160.591) 128.778,166.83 133.602,171.653 141.148,171.653 141.673,172.178 154.449,172.178 154.991,172.72 154.991,176.479 154.432,177.038 153.033,177.038 152.474,177.597 152.474,181.938 P17.21@153.924,183.388
E: P4.6 P12.9 P21.20 U8.45 | length 128.3
  Top Layer w0.2: v1(121.213,151.659) 122.245,150.627 U8.45@122.245,149.041 ; v1(132.512,139.776) 138.684,133.604 P21.20@138.684,130.048 140.134,131.498 142.24,131.498 142.674,131.064 142.674,129.36 143.436,128.598 147.523,128.598 147.754,128.829 147.754,132.895 v1(149.123,134.264) ; P12.9@188.595,127.635 192.837,131.877 192.837,132.385 P4.6@197.612,137.16
  Bottom Layer w0.2: v1(121.213,151.659) 118.309,148.754 118.309,139.11 119.226,138.192 123.419,138.192 124.472,137.139 129.875,137.139 v1(132.512,139.776) ; v1(149.123,134.264) 149.53,133.858 155.321,133.858 156.159,133.02 167.538,133.02 168.918,131.64 190.914,131.64 196.434,137.16 P4.6@197.612,137.16
ERASE: P22.17 P33.2 U8.92 | length 52.5
  Top Layer w0.2: P22.17@110.744,196.088 111.582,195.25 111.582,192.184 116.668,187.099 116.668,173.228 117.595,172.3 117.595,168.1 116.745,167.25 U8.92@116.745,164.141
  Bottom Layer w0.2: P22.17@110.744,196.088 120.777,186.055 P33.2@123.952,186.055
FIQ: P3.5 P5.3 P17.25 R1.1 S4.1 U8.75 | length 206.4
  Top Layer w0.2: P3.5@109.093,239.776 113.665,235.204 R1.1@113.665,233.807 ; U8.75@126.295,162.591 127.191,162.591 127.191,163.716 128.438,164.963 140.811,164.963 146.101,170.253 146.101,185.725 P17.25@153.924,193.548 153.06,194.412 153.06,201.219 144.145,210.134 142.138,210.134 141.605,210.668 141.605,217.009 139.048,217.009 138.633,217.424 v1(138.633,233.807)
  Bottom Layer w0.2: S4.1@59.436,228.6 59.436,233.299 68.631,242.494 88.595,242.494 89.687,241.402 ; P5.3@90.805,240.284 89.687,241.402 ; v1(138.633,233.807) R1.1@113.665,233.807 109.906,237.566 88.595,237.566 87.198,238.963 87.198,240.995 87.605,241.402 89.687,241.402
GND: C1.1 C2.2 C3.2 C4.2 C5.2 C6.2 C7.1 C8.1 C9.1 C12.1 C13.1 C15.1 C16.1 D2.2 D3.2 D4.1 D5.2 D6.2 D7.2 D8.2 D9.2 D10.2 D11.2 D12.2 D13.2 D14.2 J1.5 J1.10 J1.11 J2.6 J2.10 J2.11 J3.5 J3.10 J3.11 J4.4 J4.5 J4.6 P2.4 P4.1 P4.5 P4.16 P5.5 P7.6 P8.2 P13.2 P16.2 P16.16 P17.2 P17.18 P18.1 P19.16 P20.6 P21.7 P22.8 P22.21 P23.4 P23.6 P23.8 P23.10 P23.12 P23.14 P23.16 P23.18 P23.20 P24.1 P28.1 P31.4 R8.2 R15.1 R16.1 R28.2 R30.1 S1.2 S2.2 S3.2 S4.2 U3.2 U4.8 U5.2 U6.8 U7.2 U8.2 U8.16 U8.32 U8.52 U8.68 U8.83 U8.96 U9.15 U10.2 U11.1 U11.2 U11.3 U11.4 U11.7 Y1.2 | length 1267.6
  Top Layer w0.2: C4.2@53.888,79.248 58.42,83.78 U3.2@58.42,88.9 ; J4.6@62.243,198.933 62.243,188.953 ; C3.2@64.262,131.572 62.078,133.756 62.078,149.962 D4.1@63.5,151.384 63.5,153.619 62.687,154.432 62.687,169.469 64.11,170.891 64.11,175.285 62.243,177.152 J4.5@62.243,186.893 62.243,188.953 ; J4.4@64.953,191.663 62.243,188.953 ; S2.2@69.088,238.252 73,234.34 73,225.908 S1.2@71.628,224.536 84.328,211.836 S3.2@84.328,208.28 84.328,194.564 P16.2@87.757,191.135 ; C15.1@71.668,79.248 71.668,83.82 72.136,84.288 U5.2@72.136,88.392 ; P28.1@73.66,135.636 73.66,132.969 P24.1@85.598,121.031 85.598,111.887 D12.2@80.645,106.934 ; C8.1@97.369,177.419 97.369,181.737 97.409,181.777 Y1.2@97.409,186.055 ; v1(99.365,155.118) 101.352,153.13 107.182,153.13 109.142,155.091 U8.16@111.195,155.091 ; R16.1@104.902,82.804 104.902,80.01 P13.2@103.632,78.74 101.6,80.772 U7.2@101.6,87.884 101.6,91.694 101.132,92.162 C6.2@101.132,96.012 101.132,101.219 100.965,101.386 D14.2@100.965,106.426 105.664,111.125 P21.7@105.664,130.048 ; U8.2@111.195,162.091 110.248,162.091 108.667,163.672 108.667,172.283 v1(107.34,173.609) 108.603,174.872 108.603,176.655 110.947,178.998 114.745,178.858 114.745,172.052 114.194,171.5 114.194,169.431 114.745,168.88 U8.96@114.745,164.141 ; U8.32@115.745,149.041 115.745,151.514 115.291,151.968 115.291,156.083 v1(115.926,156.718) ; v1(119.151,158.369) 121.245,160.463 ; U8.83@121.245,164.141 121.245,160.463 ; U8.52@126.295,151.091 125.337,151.091 121.949,154.479 121.949,155.96 121.245,156.664 121.245,159.532 ; v1(131.775,161.95) 131.775,160.712 129.954,158.891 127.591,158.891 127.391,159.091 U8.68@126.295,159.091 121.686,159.091 121.245,159.532 ; P8.2@132.842,235.712 132.08,234.95 132.08,214.579 132.893,213.766 133.731,213.766 ; J2.10@136.955,85.7 139.245,87.99 139.245,104.32 U10.2@140.335,105.41 ; C16.1@139.7,168.362 138.989,169.073 138.989,176.795 C13.1@140.208,178.014 140.208,180.34 139.7,180.848 C12.1@139.7,183.174 133.604,189.27 P22.8@133.604,196.088 130.886,198.806 130.886,210.922 133.731,213.766 ; C1.1@140.629,216.027 135.992,216.027 133.731,213.766 ; U11.1@143.51,215.773 143.51,220.853 U11.7@146.05,223.393 148.59,220.853 U11.3@148.59,215.773 ; J1.11@145.493,85.7 145.493,91.518 R28.2@148.463,94.488 ; R30.1@151.892,94.869 154.61,97.587 154.61,109.296 P18.1@153.543,110.363 158.877,115.697 U4.8@158.877,124.333 155.143,128.067 155.143,133.909 P17.2@153.924,135.128 ; P17.18@153.924,175.768 159.18,170.512 159.18,160.352 P23.20@163.576,155.956 ; P23.4@183.896,155.956 185.166,157.226 185.166,186.69 U6.8@186.182,187.706 ; P4.1@197.612,124.46 196.545,125.527 196.545,133.553 P4.5@197.612,134.62 199.062,136.07 199.062,161.11 P4.16@197.612,162.56 ; 121.245,159.532 121.245,160.463
  Bottom Layer w0.2: S4.2@54.356,228.6 58.42,224.536 S1.2@71.628,224.536 ; U3.2@58.42,88.9 63.297,84.023 67.767,84.023 U5.2@72.136,88.392 ; D3.2@60.325,106.426 62.281,108.382 69.037,108.382 D13.2@70.485,106.934 71.679,108.128 79.451,108.128 D12.2@80.645,106.934 81.839,108.128 88.595,108.128 D2.2@89.789,106.934 90.729,107.874 99.517,107.874 D14.2@100.965,106.426 ; D4.1@63.5,151.384 67.691,155.575 P16.16@87.757,155.575 88.976,155.575 90.424,154.127 92.888,154.127 94.005,155.245 94.005,155.727 94.691,156.723 97.76,156.723 v1(99.365,155.118) ; C3.2@64.262,131.572 69.596,131.572 P28.1@73.66,135.636 ; J4.4@64.953,191.663 64.953,190.749 65.227,190.475 87.097,190.475 P16.2@87.757,191.135 94.386,184.506 95.86,184.506 Y1.2@97.409,186.055 ; C5.2@68.54,79.248 C15.1@71.668,79.248 72.659,78.257 80.035,78.257 R15.1@81.026,79.248 82.372,77.902 94.118,77.902 C2.2@95.464,79.248 95.972,78.74 P13.2@103.632,78.74 ; S2.2@69.088,238.252 70.46,236.88 82.321,236.88 P5.5@85.725,240.284 ; P19.16@96.393,210.185 86.233,210.185 S3.2@84.328,208.28 84.328,198.171 85.344,197.155 99.517,197.155 P22.21@100.584,196.088 102.133,197.637 132.055,197.637 P22.8@133.604,196.088 ; C8.1@97.369,177.419 97.769,177.819 98.744,177.819 99.144,177.419 C7.1@99.989,177.419 103.799,173.609 v1(107.34,173.609) ; R16.1@104.902,82.804 109.069,82.804 J2.11@111.965,85.7 127.195,85.7 J2.6@128.615,84.28 130.035,85.7 J2.10@136.955,85.7 J1.11@145.493,85.7 151.028,85.7 J1.5@152.448,87.12 153.868,85.7 J1.10@170.483,85.7 175.768,85.7 176.276,86.208 J3.11@181.561,86.208 187.096,86.208 J3.5@188.516,87.628 189.936,86.208 J3.10@206.551,86.208 ; P21.7@105.664,130.048 109.982,125.73 117.094,125.73 P7.6@121.412,121.412 124.206,121.412 124.714,121.92 P20.6@127.508,121.92 ; v1(115.926,156.718) 117.5,156.718 v1(119.151,158.369) ; P2.4@125.73,239.776 126.78,238.726 128.829,238.726 129.32,239.217 129.32,239.776 130.387,240.843 131.369,240.843 132.029,240.182 132.029,236.525 132.283,236.271 ; v1(131.775,161.95) 138.187,168.362 C16.1@139.7,168.362 ; P8.2@132.842,235.712 132.283,236.271 ; P31.4@137.668,239.903 136.728,240.843 132.486,240.843 132.283,240.64 132.283,236.271 ; C13.1@140.208,178.014 148.224,178.014 150.47,175.768 P17.18@153.924,175.768 ; C1.1@140.629,216.027 141.935,216.027 142.189,215.773 U11.1@143.51,215.773 ; U11.7@146.05,223.393 150.114,227.457 156.972,227.457 D11.2@159.766,230.251 160.96,231.445 166.7,231.445 D10.2@167.894,230.251 169.85,232.207 174.066,232.207 D9.2@175.514,230.759 176.454,231.699 181.178,231.699 D8.2@182.626,230.251 183.82,231.445 188.544,231.445 D7.2@189.738,230.251 190.932,231.445 196.164,231.445 D6.2@197.358,230.251 198.552,231.445 203.784,231.445 D5.2@204.978,230.251 ; R28.2@148.463,94.488 149.987,94.488 150.368,94.869 R30.1@151.892,94.869 ; U11.3@148.59,215.773 U11.4@151.13,215.773 ; P18.1@153.543,110.363 165.695,110.363 C9.1@168.783,107.275 168.783,109.322 169.875,110.414 175.336,110.414 U9.15@176.657,109.093 ; P23.20@163.576,155.956 P23.18@166.116,155.956 P23.16@168.656,155.956 P23.14@171.196,155.956 P23.12@173.736,155.956 P23.10@176.276,155.956 P23.8@178.816,155.956 P23.6@181.356,155.956 P23.4@183.896,155.956 185.369,157.429 185.369,159.563 188.366,162.56 P4.16@197.612,162.56 ; P4.5@197.612,134.62 201.041,134.62 201.295,134.874 R8.2@204.724,134.874
IRQ0: P3.2 P5.4 P16.22 P28.3 R12.2 S7.1 U8.22 | length 251.4
  Top Layer w0.2: S7.1@59.436,208.28 68.224,217.068 68.224,217.576 69.088,218.44 70.18,218.44 ; P28.3@73.66,140.716 71.806,142.57 71.806,216.814 70.18,218.44 ; P16.22@87.757,140.335 95.352,147.93 v1(95.352,155.245) ; P5.4@88.265,240.284 86.843,241.706 69.85,241.706 67.843,239.7 67.843,220.777 70.18,218.44 ; U8.22@111.195,152.091 112.674,152.091 114.605,154.021 114.605,157.251 v1(113.792,158.064) ; P3.2@116.713,239.776 125.476,231.013 R12.2@125.476,226.568
  Bottom Layer w0.2: P28.3@73.66,140.716 80.721,140.716 81.102,140.335 P16.22@87.757,140.335 ; P5.4@88.265,240.284 89.84,238.709 104.851,238.709 105.283,239.141 105.283,240.462 105.647,240.826 115.214,240.826 115.833,240.208 116.713,240.208 P3.2@116.713,239.776 ; v1(95.352,155.245) 96.719,155.245 98.146,153.818 113.457,153.818 114.605,154.965 114.605,157.251 v1(113.792,158.064)
IRQ1: P3.8 P5.2 P22.5 R4.1 S1.1 U8.80 | length 172.8
  Top Layer w0.2: v1(91.999,206.731) 91.999,231.953 R4.1@93.853,233.807 93.345,234.315 P5.2@93.345,240.284 ; U8.80@122.745,164.141 122.745,167.45 121.595,168.6 121.595,176.774 121.029,177.341 121.029,179.011 125.222,183.205 125.222,186.944 v1(128.499,190.221) ; P22.5@141.224,196.088 141.224,190.475 v1(141.478,190.221)
  Bottom Layer w0.2: S1.1@71.628,229.616 75.819,233.807 R4.1@93.853,233.807 ; v1(91.999,206.731) 91.999,202.997 96.472,198.524 140.21,198.524 141.224,197.51 P22.5@141.224,196.088 ; P5.2@93.345,240.284 94.412,239.217 100.914,239.217 P3.8@101.473,239.776 ; v1(128.499,190.221) v1(141.478,190.221)
JTAGSEL: P22.2 P30.2 U8.77 | length 59.2
  Top Layer w0.2: U8.77@124.245,164.141 124.245,168.504 124.46,168.719 124.46,169.875 ; P30.2@124.46,172.847 124.46,169.875 ; P22.2@148.844,196.088 142.97,190.214 142.97,188.928 141.783,187.741 141.783,167.183 141.58,166.98 137.287,166.98 135.763,168.504 125.832,168.504 124.46,169.875
KBD1: P2.3 P3.7 P17.23 P20.5 R3.1 S2.1 U8.73 | length 281.2
  Top Layer w0.2: R3.1@100.457,233.807 104.013,237.363 P3.7@104.013,239.776 ; v1(125.755,134.62) 126.859,133.516 126.859,130.749 127.051,130.557 127.051,127.203 126.441,126.594 126.441,120.447 P20.5@127.508,119.38 ; U8.73@126.295,161.591 127.834,161.591 130.099,163.855 135.974,163.855 137.447,162.382 140.97,162.382 v1(147.498,168.91) ; P2.3@128.27,239.776 130.023,241.529 153.035,241.529 153.975,240.589 153.975,197.028 154.991,196.012 154.991,189.535 P17.23@153.924,188.468 149.987,188.468 148.107,186.588 ; v1(139.141,142.011) 139.141,152.832 150.698,164.389 v1(150.698,168.91) ; v1(147.498,168.91) 147.498,185.979 148.107,186.588 ; v1(147.498,168.91) 148.107,169.52 148.107,186.588
  Bottom Layer w0.2: S2.1@74.168,238.252 77.267,241.351 86.309,241.351 86.792,240.868 86.792,237.338 87.706,236.423 97.841,236.423 R3.1@100.457,233.807 ; P3.7@104.013,239.776 105.463,241.226 126.82,241.226 P2.3@128.27,239.776 ; v1(125.755,134.62) 127.454,136.319 133.448,136.319 v1(139.141,142.011) ; v1(147.498,168.91) v1(150.698,168.91)
KBD2: P2.2 P3.6 P17.24 R2.1 S3.1 U8.74 | length 200.5
  Top Layer w0.2: S3.1@89.408,208.28 89.408,236.753 92.075,239.42 92.075,240.767 92.659,241.351 104.978,241.351 P3.6@106.553,239.776 106.553,234.823 R2.1@107.569,233.807 ; U8.74@126.295,162.091 127.471,162.091 129.943,164.563 140.977,164.563 147.022,170.609 147.022,186.069 151.961,191.008 P17.24@153.924,191.008 ; v1(129.032,203.454) 130.48,204.902 130.48,237.922 130.048,238.354 130.048,239.014 P2.2@130.81,239.776
  Bottom Layer w0.2: P3.6@106.553,239.776 108.003,238.326 129.36,238.326 P2.2@130.81,239.776 ; v1(129.032,203.454) 143.374,203.454 145.254,201.574 145.254,195.478 149.724,191.008 P17.24@153.924,191.008
KBD4: P3.4 P16.20 P28.5 R10.2 S5.1 U8.20 | length 189.3
  Top Layer w0.2: P28.5@73.66,145.796 72.593,146.863 72.593,206.705 S5.1@74.168,208.28 ; v1(101.829,147.574) 103.226,147.574 106.858,151.206 108.097,151.206 109.982,153.091 U8.20@111.195,153.091 ; P3.4@111.633,239.776 111.633,238.176 115.418,234.391 115.418,225.45 R10.2@125.476,215.392
  Bottom Layer w0.2: P28.5@73.66,145.796 80.721,145.796 81.102,145.415 P16.20@87.757,145.415 87.757,145.085 99.339,145.085 v1(101.829,147.574) ; S5.1@74.168,208.28 77.923,212.035 106.236,212.035 109.593,215.392 R10.2@125.476,215.392
KBD5: P3.3 P16.21 P28.4 R11.2 S6.1 U8.21 | length 193.1
  Top Layer w0.2: P28.4@73.66,143.256 75.413,145.009 75.413,211.049 74.676,211.785 S6.1@74.676,216.916 ; v1(106.299,147.574) 106.299,148.832 110.058,152.591 U8.21@111.195,152.591 ; P3.3@114.173,239.776 117.5,236.449 117.5,228.956 R11.2@125.476,220.98
  Bottom Layer w0.2: P28.4@73.66,143.256 80.721,143.256 81.102,142.875 P16.21@87.757,142.875 101.6,142.875 v1(106.299,147.574) ; S6.1@74.676,216.916 78.74,220.98 R11.2@125.476,220.98
KBD7: P3.1 P16.23 P28.2 R13.2 S8.1 U8.23 | length 203.7
  Top Layer w0.2: P16.23@87.757,137.795 96.236,146.274 ; U8.23@111.195,151.591 109.624,151.591 107.62,149.587 107.62,146.482 107.412,146.274 96.236,146.274 ; P3.1@119.253,239.776 125.476,233.553 R13.2@125.476,232.664 126.492,231.648 126.492,214.579 123.647,211.734 116.662,211.734 115.443,210.515 115.443,209.144 110.617,204.318 104.546,204.318 96.994,196.765 96.994,190.271 98.425,188.84 98.425,170.561 95.307,167.443 95.307,157.313 96.855,155.766 96.855,146.893 96.236,146.274
  Bottom Layer w0.2: P28.2@73.66,138.176 80.721,138.176 81.102,137.795 P16.23@87.757,137.795 ; S8.1@87.884,228.6 121.412,228.6 R13.2@125.476,232.664
LED0: P17.13 U8.63 | length 32.9
  Top Layer w0.2: U8.63@126.295,156.591 128.499,156.591 129.599,157.691 133.053,157.691 v1(134.214,158.852)
  Bottom Layer w0.2: v1(134.214,158.852) 135.144,158.852 136.414,160.122 136.414,162.779 137.973,164.338 152.654,164.338 P17.13@153.924,163.068
LED1: P7.2 P17.14 R18.1 U6.2 U8.64 | length 241.7
  Top Layer w0.2: v1(124.206,155.778) 124.206,156.202 125.095,157.091 U8.64@126.295,157.091 ; v1(157.48,165.608) 157.84,165.248 157.84,152.074 163.352,146.563 163.352,120.909 v1(160.757,118.313) ; v1(161.468,165.608) 162.052,166.192 v1(162.052,202.946) ; U6.2@186.182,202.946 185.115,204.013 185.115,216.281 186.131,217.297 193.04,217.297 R18.1@194.056,216.281
  Bottom Layer w0.2: P7.2@111.252,121.412 112.319,120.345 114.599,120.345 114.882,120.628 114.882,122.326 115.418,122.862 117.473,122.862 117.782,122.553 117.782,120.669 120.138,118.313 v1(160.757,118.313) ; v1(124.206,155.778) 125.028,154.956 142.764,154.956 146.854,159.046 155.226,159.046 155.374,159.193 155.374,164.158 P17.14@153.924,165.608 v1(157.48,165.608) v1(161.468,165.608) ; v1(162.052,202.946) U6.2@186.182,202.946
